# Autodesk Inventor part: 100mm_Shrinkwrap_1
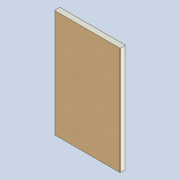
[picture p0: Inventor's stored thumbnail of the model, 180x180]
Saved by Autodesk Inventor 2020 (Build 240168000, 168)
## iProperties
Created: 2020-11
Part Number: 100mm_Shrinkwrap_1
Material: Generic
Document SubType Name: Modeling
Designer: Yolande
Density: 1 g/cm^3
Appearance: Default
description: 0:0:Lambdaboard 100mm Kraft
manufacturer: 0:0:Lambdaboard T/A Rigifoam
model: 0:0:
url: 0:0:www.lambdaboard.com
Author: Yolande
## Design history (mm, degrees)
derived "100mm.iam"
body "Solid1"
node "Lambdaboard 100mm Kraft.ipt:1" dims "d0" = 10
